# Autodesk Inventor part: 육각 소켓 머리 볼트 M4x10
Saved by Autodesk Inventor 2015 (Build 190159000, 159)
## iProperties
Created: 2024-12
Part Number: 육각 소켓 머리 볼트 M4x10
Material: 일반
Document SubType Name: Modeling
Designer: 102-5
Density: 1 g/cm^3
Appearance: 기본값
Author: 102-5
Author: jhkim
Description: 6각머리 태핑 나사
Creation Date: 2024-11-28
Sending System: Autodesk Inventor 2025
Preprocessor: ST-DEVELOPER v20
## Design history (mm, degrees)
node "육각 소켓 머리 볼트 M4x101"
body "Solid1"
node "기준1"
